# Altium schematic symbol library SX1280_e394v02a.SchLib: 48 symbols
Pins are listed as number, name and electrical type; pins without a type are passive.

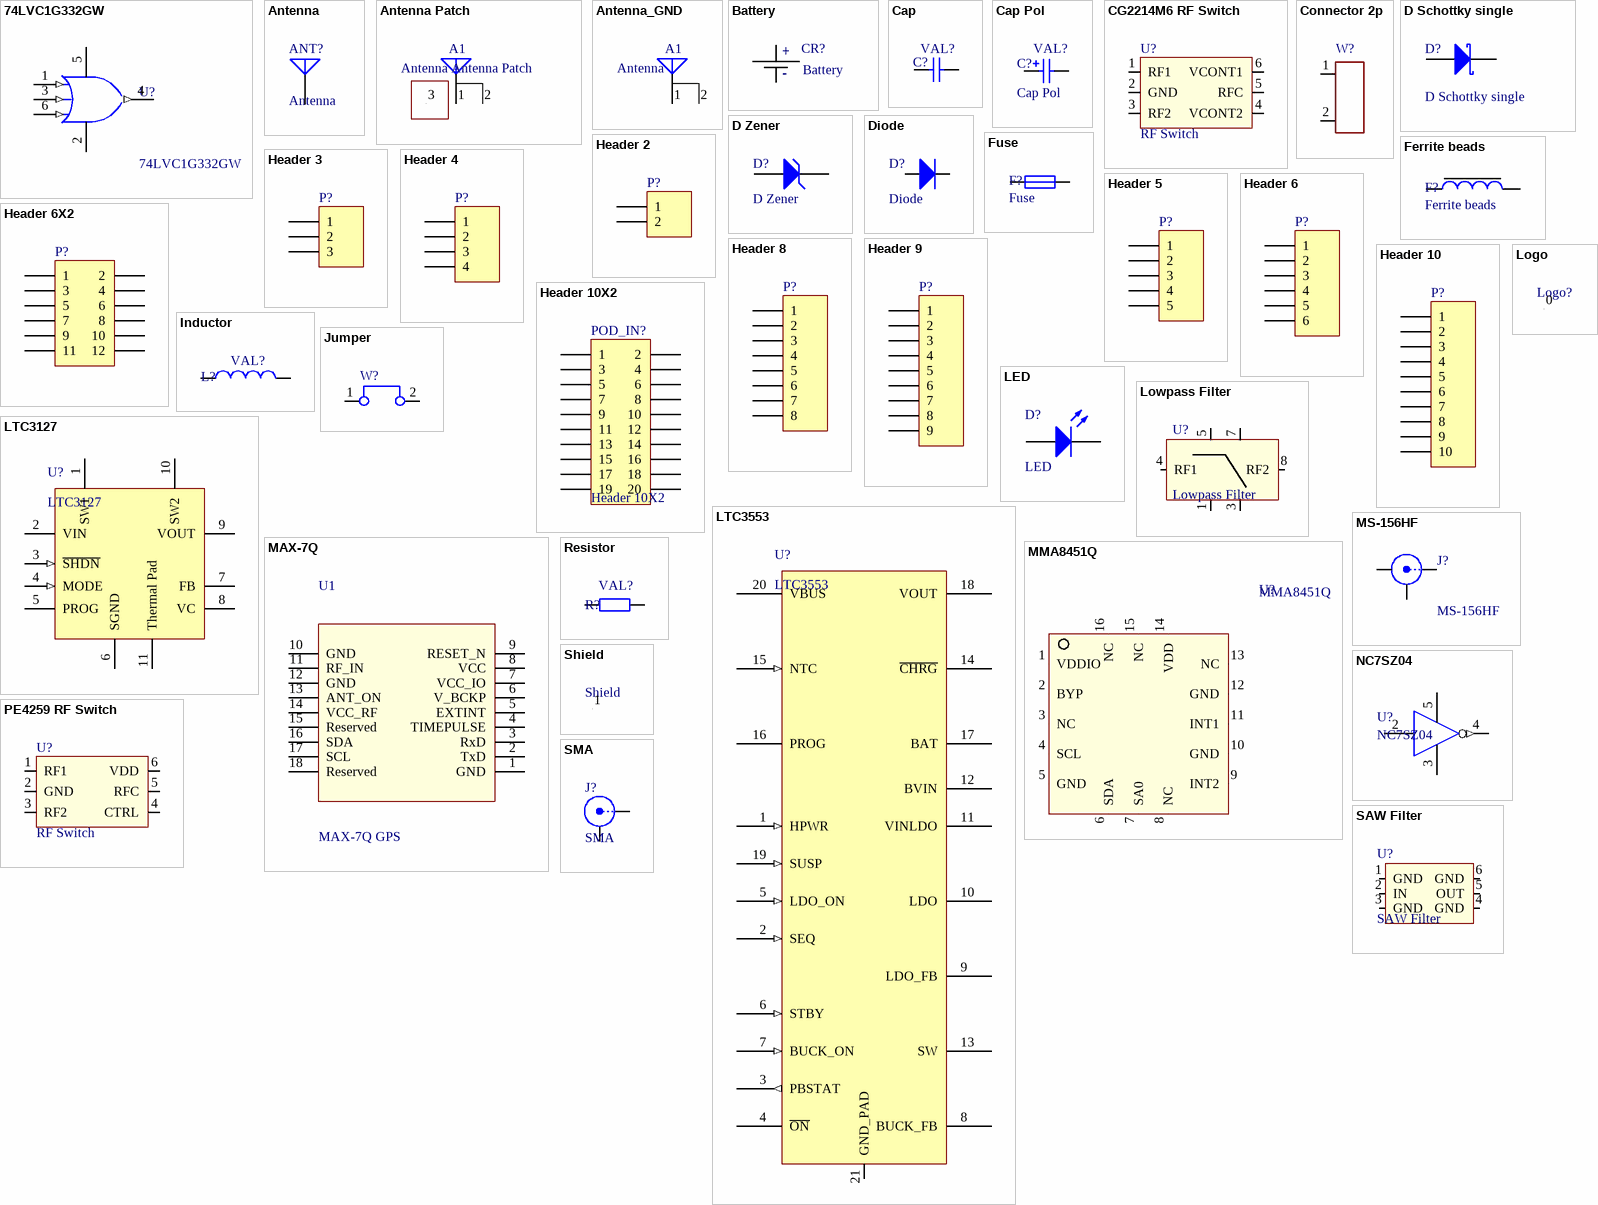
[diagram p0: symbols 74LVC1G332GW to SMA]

## 74LVC1G332GW
designator U?
Triple 3-Input OR Gate, 6-Pin
footprint SOT363-6 (SOT363, 6-Leads, Body 2x1.3mm, Pitch 0.65mm, Lead Span 2.1mm, IPC Medium Density)
pins: 1 A (in), 2 GND (power), 3 B (in), 4 Y (out), 5 VCC (power), 6 C (in)

## Antenna
designator ANT?
Generic Antenna
footprint pin_0.9mm (Generic Pin 0.9mm; 1 Lead)
footprint pin_1.1mm (Generic Pin 1.1mm; 1 Lead)
footprint ANT-LINX-HESM (Helix Antenna - Linx 434MHz)
footprint pin_1mm (Generic Pin 1.1mm; 1 Lead)
footprint ANT_2.4GHz_microstrip (Antenna 2.4 GHz ISM band - Microstrip)
pins: 1 A

## Antenna Patch
designator A1, comment Antenna Antenna Patch
Generic Antenna
footprint ANT Blipper (Antenna Blipper 868/915MHz)
pins: 1 A, 2 GND, 3 Patch

## Antenna_GND
designator A1, comment Antenna
Generic Antenna with GND
footprint ANT-315-SP (ANT-315-SP - Antenna Factor)
footprint ANT F-inverted (Antenna F-inverted 868/915MHz)
footprint ANT-PRINTED-SM (Custom Printed Antenna for SX12xx applications)
pins: 1 A, 2 GND

## Battery
designator CR?
Baterry standard modif
footprint keystone_3002 (Keystone 3002 Battery Holder - CR2032 or other 20mm diam. battery)
footprint B2B-PH-K-S (B2B-PH-K-S; JST; Battery Connector; Header; 2 Position)
footprint S2B-PH-K-S (S2B-PH-K-S; JST; Battery Connector side entry; Header; 2 Position)
pins: 1 +, 2 -

## Cap
designator C?  value VAL?  (hidden comment: Cap)
Capacitor SMD
simulation model CAP (Semiconductor Capacitor)
signal-integrity model Cap Semi
footprint rlc_402_smd (Chip SMD component 402; Body 1.0 x 0.5 mm (LxW typ))
footprint rlc_603_smd (Chip SMD component 603; Body 1.6 x 0.8mm (LxW typ))
footprint rlc_805_smd (Chip SMD component 805; Body 2.0 x 1.25 mm (LxW typ))
footprint rlc_1206_smd (Chip SMD component 1206; Body 3.2 x 1.6 mm (LxW typ))
footprint rlc_201_smd (Chip SMD component 201; Body 0.6 x 0.3 mm (LxW typ))
pins: 1, 2

## Cap Pol
designator C?  value VAL?
Polarized Capacitor (Surface Mount)
simulation model CAP (Capacitor)
signal-integrity model Cap Pol
footprint rlc_1210_smd (Chip SMD component 1210; Body 3.2 x 2.5 mm (LxW typ))
footprint rlc_1812_smd (Chip SMD component 1812; Body 4.5 x 3.2 mm (LxW typ))
footprint rlc_2225_smd (Chip SMD component 2225; Body 5.6 x 6.4 mm (LxW typ))
footprint CD3216-1206 (Chip Diode; Body 3.2 x 1.6 mm (LxW typ))
footprint CD2012-0805 (Chip Diode; Body 2.0 x 1.3 mm (LxW typ))
footprint rlc_1206_smd capa pol (Chip SMD component 1206; Body 3.2 x 1.6 mm (LxW typ))
pins: 1, 2
1 alternate drawing of the same symbol

## CG2214M6 RF Switch
designator U?, comment RF Switch
CG2214M6 RF Switch
footprint MiniMold-6 (MiniMold-6 Package 1.5x1.1mm)
pins: 1 RF1, 2 GND, 3 RF2, 4 VCONT2, 5 RFC, 6 VCONT1

## Connector 2p
designator W?  (value not drawn)
2pins Connector
footprint Connector 2p 2_54mm (Generic connector 2.54mm, 2 Leads 1mm;)
pins: 1, 2

## D Schottky single
designator D?
Schottky Diode
footprint SOD123 (SOD123; Chip Diode; Body  2.7 x 1.6 mm (LxW typ))
pins: 1 A, 2 K

## D Zener
designator D?
Zener Diode
footprint CD1608-0603 (Chip Diode; Body 1.6 x 0.8 mm (LxW typ))
footprint CD2012-0805 (Chip Diode; Body 2.0 x 1.3 mm (LxW typ))
pins: 1 A, 2 K

## Diode
designator D?
Protection Diode
footprint CD1005-0402 (Chip Diode; Body 1.0 x 0.5 mm (LxW typ))
footprint CD1608-0603 (Chip Diode; Body 1.6 x 0.8 mm (LxW typ))
footprint CD2012-0805 (Chip Diode; Body 2.0 x 1.3 mm (LxW typ))
footprint CD3216-1206 (Chip Diode; Body 3.2 x 1.6 mm (LxW typ))
footprint PowerDI 123 (Chip Diode; PowerDI 123)
footprint DO214-AA (Chip Diode; Body 4.3 x3.6mm (LxW typ))
pins: 1 A, 2 K

## Ferrite beads
designator F?
Value: VAL?
footprint rlc_1206_smd (Chip SMD component 1206; Body 3.2 x 1.6 mm (LxW typ))
footprint rlc_805_smd (Chip SMD component 805; Body 2.0 x 1.25 mm (LxW typ))
footprint rlc_603_smd (Chip SMD component 603; Body 1.6 x 0.8mm (LxW typ))
footprint rlc_402_smd (Chip SMD component 402; Body 1.0 x 0.5 mm (LxW typ))
pins: 1, 2

## Fuse
designator F?
simulation model FUSE (Spice Subcircuit)
footprint rlc_1206_smd (Chip SMD component 1206; Body 3.2 x 1.6 mm (LxW typ))
footprint rlc_805_smd (Chip SMD component 805; Body 2.0 x 1.25 mm (LxW typ))
footprint rlc_603_smd (Chip SMD component 603; Body 1.6 x 0.8mm (LxW typ))
footprint rlc_402_smd (Chip SMD component 402; Body 1.0 x 0.5 mm (LxW typ))
pins: 1, 2

## Header 2
designator P?
Header, 2-Pin
footprint HDR1X2 (Connector; Header; 2 Position)
signal-integrity model Connector
pins: 1, 2

## Header 3
designator P?
Header, 3-Pin
footprint HDR1X3 (Connector; Header; 3 Position)
signal-integrity model Connector
pins: 1, 2, 3

## Header 4
designator P?
Header, 4-Pin
footprint HDR1X4 (Connector; Header; 4 Position)
signal-integrity model Connector
pins: 1, 2, 3, 4

## Header 5
designator P?
Header, 5-Pin
footprint HDR1X5 (Connector; Header; 5 Position)
signal-integrity model Connector
pins: 1, 2, 3, 4, 5

## Header 6
designator P?
Header, 6-Pin
footprint HDR1X6 (Connector; Header; 6 Position)
signal-integrity model Connector
pins: 1, 2, 3, 4, 5, 6

## Header 6X2
designator P?
Header, 6-Pin, Dual row
footprint HDR2X6 (Connector; Header; 6x2 Position)
signal-integrity model Connector
pins: 1, 2, 3, 4, 5, 6, 7, 8, 9, 10, 11, 12

## Header 8
designator P?
Header, 8-Pin
footprint HDR1X8 (Connector; Header; 8 Position)
signal-integrity model Connector
pins: 1, 2, 3, 4, 5, 6, 7, 8

## Header 9
designator P?
Header, 9-Pin
footprint HDR1X9 (Connector; Header; 9 Position)
signal-integrity model Connector
pins: 1, 2, 3, 4, 5, 6, 7, 8, 9

## Header 10
designator P?
Header, 10-Pin
footprint HDR1X10 (Connector; Header; 10 Position)
signal-integrity model Connector
footprint HDR1X10_TFT_Display (Connector; Header; 10 Position; Adafruit TFT Display)
pins: 1, 2, 3, 4, 5, 6, 7, 8, 9, 10

## Header 10X2
designator POD_IN?
Header, 10-Pin, Dual row
footprint HDR2X10 (Connector; Header; 10x2 Position)
footprint HDR2X10 modif (Connector; Header; 10x2 Position - modified)
footprint SSW-110-01-F-D (Connector SMD; Header; 10x2 Position; Samtec)
pins: 1, 2, 3, 4, 5, 6, 7, 8, 9, 10, 11, 12, 13, 14, 15, 16, 17, 18, 19, 20

## Inductor
designator L?  value VAL?  (hidden comment: Inductor)
Inductor SMD; Code_IEC: 1005
simulation model INDUCTOR (Inductor)
signal-integrity model Inductor
footprint rlc_402_smd (Chip SMD component 402; Body 1.0 x 0.5 mm (LxW typ))
footprint rlc_201_smd (Chip SMD component 201; Body 0.6 x 0.3 mm (LxW typ))
footprint rlc_603_smd (Chip SMD component 603; Body 1.6 x 0.8mm (LxW typ))
footprint rlc_805_smd (Chip SMD component 805; Body 2.0 x 1.25 mm (LxW typ))
footprint rlc_1206_smd (Chip SMD component 1206; Body 3.2 x 1.6 mm (LxW typ))
footprint rlc_1210_smd (Chip SMD component 1210; Body 3.2 x 2.5 mm (LxW typ))
footprint rlc_1812_smd (Chip SMD component 1812; Body 4.5 x 3.2 mm (LxW typ))
footprint L2813
footprint L4818
pins: 1, 2

## Jumper
designator W?  (value not drawn)
Jumper Wire
footprint bridge_254mm (Generic Bridge 2.54mm, 2 Leads 1mm;)
footprint bridge_508mm (Generic Bridge 5.08mm, 2 Leads 1mm;)
pins: 1, 2

## LED
designator D?
footprint CD1005-0402 (Chip Diode; Body 1.0 x 0.5 mm (LxW typ))
footprint CD1608-0603 (Chip Diode; Body 1.6 x 0.8 mm (LxW typ))
footprint CD2012-0805 (Chip Diode; Body 2.0 x 1.3 mm (LxW typ))
footprint Reverse LED 3216 - 1206-hole round (Reverse Package Chip LED; Body 3.2 x 1.6 mm (LxW typ))
footprint Reverse LED 3216 - 1206 - hole slot (Reverse Package Chip LED; Body 3.2 x 1.6 mm (LxW typ))
pins: 1 A, 2 K

## Logo
designator Logo?, comment Logo symbol  (value not drawn)
Schematic symbol for Logo
footprint logo_semtech_horiz_size1 (Logo semtech horizontal - size1 - S)
footprint logo_semtech_horiz_size2 (Logo semtech horizontal - size2 - M)
footprint logo_semtech_horiz_size3 (Logo semtech horizontal - size3 - L)
footprint logo_semtech_horiz_size4 (Logo semtech horizontal - size4 - XL)
footprint Logo DC Supply (Logo for DC Supply)
footprint Logo LoRa Size1
footprint Logo LoRa Size2
footprint Logo LoRa Size3
footprint Logo LoRa Size4 (Logo LoRa Size4 - Top Overlay)
footprint Logo LR24 - Size1 (Logo LR24 - Size1 - Top Overlay)
footprint Logo LR24 - Size2 (Logo LR24 - Size2 - Top Overlay)
pins: 0 "Logo"

## Lowpass Filter
designator U?
RF Filter - Lowpass
footprint LP Filter Johanson (Low Pass Filter ; Body 2.00 x 1.25 mm (LxW max))
pins: 1 GND, 3 GND, 4 RF1, 5 GND, 7 GND, 8 RF2

## LTC3127
designator U?
LTC3127EDD#PBF - 1A Buck-Boost DC/DC  Converter with Programmable  Input Current Limit
footprint DD10_N (SON, 10-Leads, Body 3x3 mm, Pitch 0.5mm, IPC Medium Density)
footprint DD10_L (SON, 10-Leads, Body 3x3 mm, Pitch 0.5mm, IPC High Density)
footprint DD10_M (SON, 10-Leads, Body 3x3 mm, Pitch 0.5mm, IPC Low Density)
pins: 1 SW1 (oc), 2 VIN (power), 3 ~{SHDN} (in), 4 MODE (in), 5 PROG, 6 SGND, 7 FB, 8 VC, 9 VOUT, 10 SW2 (oc), 11 Thermal Pad (power)

## LTC3553
designator U?
Micropower USB Power Manager With Li-Ion Charger,  LDO and Buck Regulator
footprint vqfn20_3x3mm (20 Leads, Body 3.0x3.0mm, Pitch 0.40mm, VQFN20)
pins: 1 HPWR (in) "High Power Logic Input", 2 SEQ (in) "Regulator Power-Up Sequence Select", 3 PBSTAT (out) "Pushbutton Status", 4 ~{ON} "ON", 5 LDO_ON (in) "Logic Input Enables LDO", 6 STBY (in) "Standby Mode", 7 BUCK_ON (in) "Logic Input Enables the Buck Regulator", 8 BUCK_FB (power) "Feedback Input for the Buck Regulator", 9 LDO_FB (power) "Feedback Input for the Low Dropout Regulator", 10 LDO (power) "Low Dropout (LDO) Linear Regulator Output", 11 VINLDO (power) "Power Input Pin for the LDO Regulator", 12 BVIN (power) "Power Input for the Buck Regulator", 13 SW (power) "Power Transmission (Switch) Pin", 14 ~{CHRG} "Open-Drain Charge Status Output", 15 NTC (in) "Input to the Negative Temperature Coefficient Thermistor Temperature Monitoring Circuit", 16 PROG "Charge Current Program", 17 BAT (power) "Single-Cell Li-Ion Battery Pin", 18 VOUT (power) "Output Voltage of the PowerPath Controller", 19 SUSP (in) "Suspend Mode", 20 VBUS (power) "Positive Supply Voltage Input", 21 GND_PAD (power) "Ground Pad"

## MAX-7Q
designator U1, comment MAX-7Q GPS
MAX-7Q; U-Blox; 7 GPS/GNSS modules
footprint MAX-7 (MAX-7; GPS U-Blox footprint)
pins: 1 GND, 2 TxD, 3 RxD, 4 TIMEPULSE, 5 EXTINT, 6 V_BCKP, 7 VCC_IO, 8 VCC, 9 RESET_N, 10 GND, 11 RF_IN, 12 GND, 13 ANT_ON, 14 VCC_RF, 15 Reserved, 16 SDA, 17 SCL, 18 Reserved

## MMA8451Q
designator U?
Xtrinsic MMA8451Q 3-Axis, 14-bit/8-bit Digital Accelerometer
footprint vqfn16_3x3mm (16 Leads, Body 3.0x3.0mm, Pitch 0.50mm, VQFN16)
pins: 1 VDDIO, 2 BYP, 3 NC, 4 SCL, 5 GND, 6 SDA, 7 SA0, 8 NC, 9 INT2, 10 GND, 11 INT1, 12 GND, 13 NC, 14 VDD, 15 NC, 16 NC

## MS-156HF
designator J?
MS-156HF Hirose RF Connector
footprint MS-156HF Hirose (Hirose MS-156HF receptacle - MS-156HF)
pins: 1 Signal "RF signal1", 2 Signal "RF signal2", 3 GND (power) "Ground signal", 4 GND (power) "Ground signal"

## NC7SZ04
designator U?
NC7SZ04 - TinyLogic HS Single Inverter - Fairchild Semi
footprint SOT23-5 (SOT23, 5-Leads, Body 2.9x1.6mm, Pitch 0.95mm, Lead Span 2.8mm, IPC Medium Density)
footprint SC70-5 (SC70 5-Leads, Body 2.0x1.25mm, Pitch 0.65mm)
pins: 2 A, 3 GND (power), 4 Y (out), 5 VCC (power)

## PE4259 RF Switch
designator U?, comment RF Switch
PE4259 Peregrine RF Switch
footprint SC70-6 (SC70 6-Leads, Body 2.0x1.25mm, Pitch 0.65mm)
pins: 1 RF1, 2 GND, 3 RF2, 4 CTRL, 5 RFC, 6 VDD

## Resistor
designator R?  value VAL?  (hidden comment: Resistor)
Resistor SMD - IEC symbol version
footprint rlc_201_smd (Chip SMD component 201; Body 0.6 x 0.3 mm (LxW typ))
footprint rlc_402_smd (Chip SMD component 402; Body 1.0 x 0.5 mm (LxW typ))
footprint rlc_603_smd (Chip SMD component 603; Body 1.6 x 0.8mm (LxW typ))
footprint rlc_805_smd (Chip SMD component 805; Body 2.0 x 1.25 mm (LxW typ))
footprint rlc_1206_smd (Chip SMD component 1206; Body 3.2 x 1.6 mm (LxW typ))
pins: 1, 2

## SAW Filter
designator U?
SAW Filter - Bandpass - TEMEX type
footprint sc44_3.8x3.8mm (sc44 footprint, 3.8x3.8mm)
footprint DCC6C_3.0x3.0mm (DCC6C footprint, 3.0x3.0mm)
pins: 1 GND, 2 IN, 3 GND, 4 GND, 5 OUT, 6 GND

## Shield
designator Shield, comment Logo symbol  (value not drawn)
Shield - EMI Gasket - Standard Surface Mount Shields
footprint BMIS-209-F - Shield (BMIS-209-F EMI Gasket - modif SolderMask - Standard Surface Mount Shields -  Laird Technologies)
pins: 1 "Shield"

## SMA
designator J?
SMA Straight Connector
footprint SMA Straight SMD (SMA Connector; Straight; SMD)
footprint SMA END LAUNCH JACK RECEPTACLE (SMA Connector - End Launch Jack Receptacle)
footprint SMA Straight (SMA Connector; Straight)
footprint SMA END LAUNCH JACK RECEPTACLE SHORT (SMA Connector - End Launch Jack Receptacle - Short)
pins: 1 Signal "RF signal", 2 GND "Ground signal"

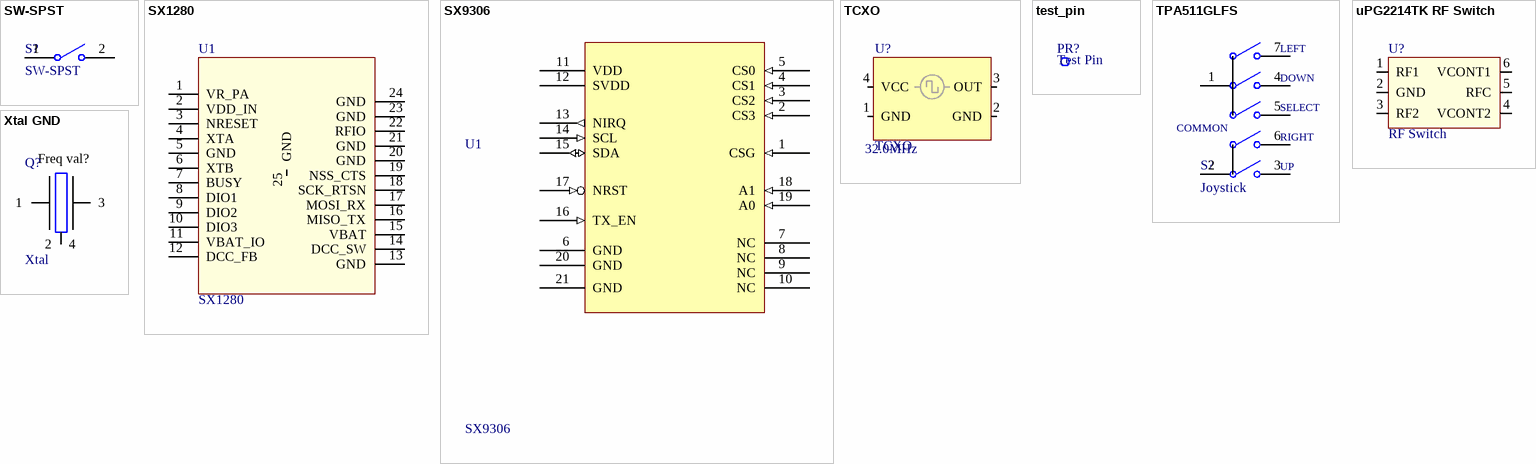
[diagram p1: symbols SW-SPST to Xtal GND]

## SW-SPST
designator S?
Single-Pole, Single-Throw Switch
pins: 1 COMMON, 2 NO

## SX1280
designator U1
SX1280 - Ultra low power RF transceiver
footprint vqfn24_4x4mm (24 Leads, Body 4.0x4.0mm, Pitch 0.50mm, VQFN24)
pins: 1 VR_PA, 2 VDD_IN, 3 NRESET, 4 XTA, 5 GND, 6 XTB, 7 BUSY, 8 DIO1, 9 DIO2, 10 DIO3, 11 VBAT_IO, 12 DCC_FB, 13 GND, 14 DCC_SW, 15 VBAT, 16 MISO_TX, 17 MOSI_RX, 18 SCK_RTSN, 19 NSS_CTS, 20 GND, 21 GND, 22 RFIO, 23 GND, 24 GND, 25 GND

## SX9306
designator U1
Ultra Low Power, Smart Proximity Sensor for SAR
footprint vqfn20_3x3mm (20 Leads, Body 3.0x3.0mm, Pitch 0.40mm, VQFN20)
footprint vqfn20_3x3mm (20 Leads, Body 3.0x3.0mm, Pitch 0.40mm, VQFN20)
pins: 1 CSG (in), 2 CS3 (in), 3 CS2 (in), 4 CS1 (in), 5 CS0 (in), 6 GND (power), 7 NC, 8 NC, 9 NC, 10 NC, 11 VDD (power), 12 SVDD (power), 13 NIRQ (out), 14 SCL (in), 15 SDA (io), 16 TX_EN (in), 17 NRST (in), 18 A1 (in), 19 A0 (in), 20 GND (power), 21 GND (power)

## TCXO
designator U?  value 32.0MHz
footprint IT3200C TCXO (SMD 3.2x2.5mm for IT3200C TCXO)
footprint TCXO 3.2x2.5mm (SMD 3.2x2.5mm for TCXO or VCTCXO)
footprint TCXO 3.2x2.5mm_2.0x1.6mm (SMD 3.2x2.5mm & 2.0x1.6mm compatible for TCXO or VCTCXO)
footprint TCXO 2.0x1.6mm (SMD 2.0x1.6mm for TCXO or VCTCXO)
pins: 1 GND, 2 GND, 3 OUT, 4 VCC

## test_pin
designator PR?, comment Test Pin
footprint pin_1mm (Generic Pin 1.1mm; 1 Lead)
footprint pin_1.1mm (Generic Pin 1.1mm; 1 Lead)
footprint pin_SMD (Generic Pin; 1 pin SMD)
pins: 1 pin  "Test Pin"

## TPA511GLFS
designator S?, comment Joystick
Joystick - Multidirection SMT Navigation Switch - TPA511GLFS
footprint TPA511GLFS (Joystick; TPA511GLFS; TPA Series; C&K Components)
pins: 1 COMMON1, 2 COMMON2, 3 UP, 4 DOWN, 5 SELECT, 6 RIGHT, 7 LEFT

## uPG2214TK RF Switch
designator U?, comment RF Switch
uPG2214TK RF Switch
footprint MiniMold-6 (MiniMold-6 Package 1.5x1.1mm)
pins: 1 RF1, 2 GND, 3 RF2, 4 VCONT2, 5 RFC, 6 VCONT1

## Xtal GND
designator Q?, comment Xtal  value Freq val?
Crystal with GND pins; 4 pins
footprint nd2520da (Crystal SMD 2.5x2.0mm)
footprint nd2016da (Crystal SMD 2.0x1.6mm)
footprint nd3225da (Crystal SMD 3.2x2.5mm)
footprint nd5032da (Crystal SMD 5.0x3.2mm)
footprint nd6035da (Crystal SMD 6.0x3.5mm)
footprint nd7050da - enlarge (Crystal SMD 7.0x5.0mm - Enlarge Pads to be compatible with 3.2x2.5mm footprint)
footprint nd3225da - nd2520da (Crystal SMD 3.2x2.5mm compatible with 2.5x2.0mm)
pins: 1, 2, 3, 4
